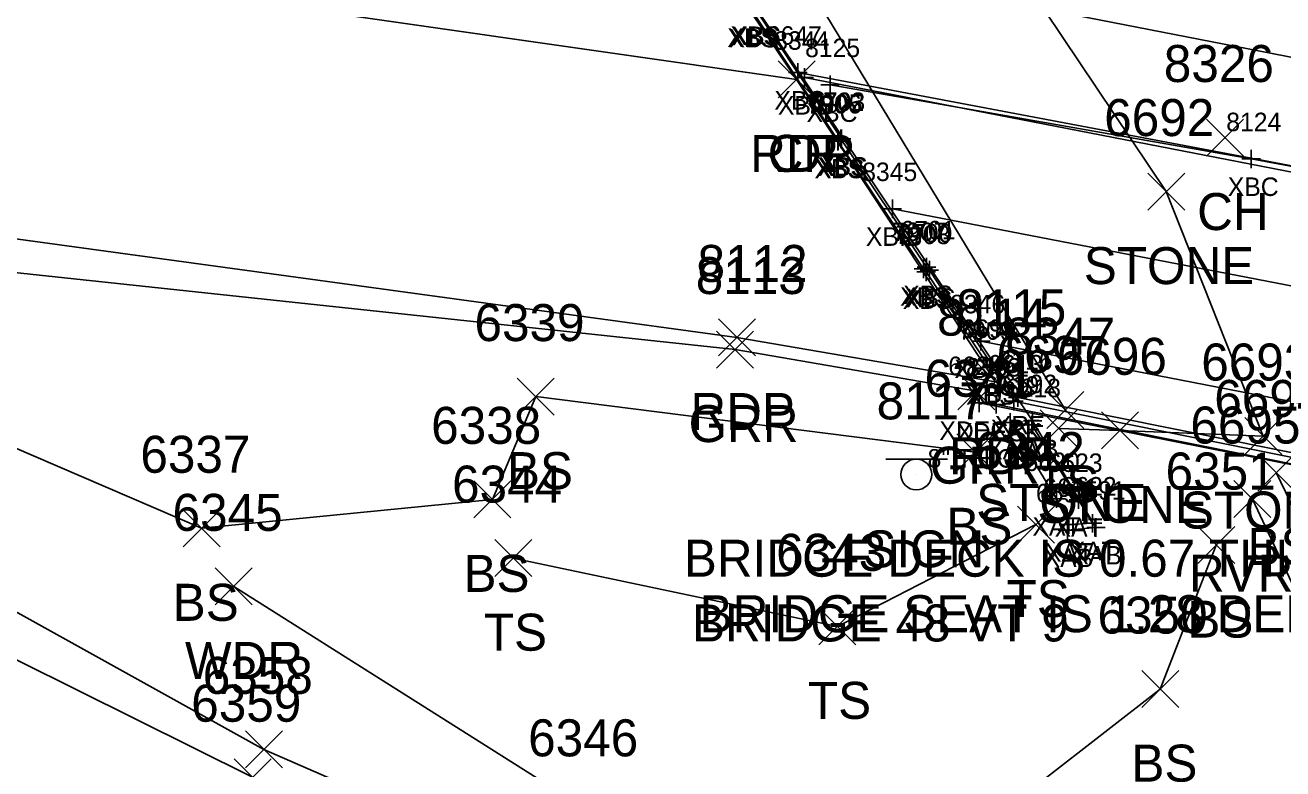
# Model space of a CAD drawing. Extents: x 1588028 to 1589597, y 137576 to 138176.
# Drawn here: x 1588875.5 to 1588943.5, y 137826.6 to 137866.8 of the extents above; entities that cross this region are included whole.
import ezdxf

# ---------------------------------------------------------------- set-up
doc = ezdxf.new("R2010")
doc.units = 0
for name, color, linetype in [('B_A', 7, 'Continuous'), ('B_C', 7, 'Continuous'), ('B_I', 7, 'Continuous'), ('B_TIC', 7, 'Continuous'), ('BB', 7, 'Continuous'), ('BELB', 7, 'Continuous'), ('BR', 7, 'Continuous'), ('BSE', 7, 'Continuous'), ('BSUBM', 7, 'Continuous'), ('L_A', 7, 'Continuous'), ('L_C', 7, 'Continuous'), ('L_I', 7, 'Continuous'), ('L_TIC', 7, 'Continuous'), ('LASF', 7, 'Continuous'), ('LAWA', 7, 'Continuous'), ('LAWE', 7, 'Continuous'), ('LELB', 7, 'Continuous'), ('P_A', 7, 'Continuous'), ('P_I', 7, 'Continuous'), ('P_TIC', 7, 'Continuous'), ('PET', 7, 'Continuous'), ('PRC', 7, 'Continuous'), ('R_A', 7, 'Continuous'), ('R_I', 7, 'Continuous'), ('R_TIC', 7, 'Continuous'), ('RGR', 7, 'Continuous'), ('S_A', 7, 'Continuous'), ('S_C', 7, 'Continuous'), ('S_I', 7, 'Continuous'), ('SSGN', 7, 'Continuous')]:
    doc.layers.add(name, color=color, linetype=linetype)

msp = doc.modelspace()

# ---------------------------------------------------------------- linework, layer by layer
at = {"layer": 'B_TIC'}
for p, q in [((1588917.306, 137864.223), (1588917.382, 137864.223)), ((1588917.661, 137863.951), (1588917.737, 137863.951)), ((1588919.047, 137863.553), (1588919.123, 137863.553)), ((1588919.475, 137860.508), (1588919.55, 137860.508)), ((1588919.492, 137860.544), (1588919.567, 137860.544)), ((1588919.625, 137860.635), (1588919.701, 137860.635)), ((1588919.666, 137860.644), (1588919.742, 137860.644)), ((1588941.815, 137859.552), (1588941.89, 137859.552)), ((1588922.419, 137856.857), (1588922.494, 137856.857)), ((1588924.267, 137853.707), (1588924.342, 137853.707)), ((1588924.095, 137853.616), (1588924.17, 137853.616)), ((1588924.244, 137853.45), (1588924.319, 137853.45)), ((1588924.42, 137853.54), (1588924.495, 137853.54)), ((1588927.2, 137849.709), (1588927.276, 137849.709)), ((1588927.664, 137848.28), (1588927.74, 137848.28)), ((1588927.829, 137848.377), (1588927.905, 137848.377)), ((1588927.118, 137846.372), (1588927.193, 137846.372)), ((1588928.033, 137846.292), (1588928.108, 137846.292)), ((1588928.98, 137846.459), (1588929.056, 137846.459)), ((1588929.195, 137846.665), (1588929.271, 137846.665)), ((1588928.786, 137845.314), (1588928.861, 137845.314)), ((1588929.949, 137845.177), (1588930.025, 137845.177)), ((1588930.001, 137845.393), (1588930.077, 137845.393)), ((1588931.286, 137841.191), (1588931.362, 137841.191)), ((1588932.485, 137841.138), (1588932.56, 137841.138)), ((1588931.878, 137839.494), (1588931.954, 137839.494)), ((1588931.963, 137839.791), (1588932.039, 137839.791)), ((1588933.239, 137839.863), (1588933.314, 137839.863)), ((1588933.427, 137839.638), (1588933.502, 137839.638))]:
    msp.add_line(p, q, dxfattribs=at)
for points in [[(1588917.303, 137863.723), (1588917.303, 137864.723)], [(1588916.803, 137864.223), (1588917.803, 137864.223)], [(1588917.158, 137863.951), (1588918.158, 137863.951)], [(1588917.658, 137863.451), (1588917.658, 137864.451)], [(1588919.044, 137863.053), (1588919.044, 137864.053)], [(1588918.544, 137863.553), (1588919.544, 137863.553)], [(1588918.971, 137860.508), (1588919.971, 137860.508)], [(1588918.988, 137860.544), (1588919.988, 137860.544)], [(1588919.122, 137860.635), (1588920.122, 137860.635)], [(1588919.163, 137860.644), (1588920.163, 137860.644)], [(1588919.471, 137860.008), (1588919.471, 137861.008)], [(1588919.488, 137860.044), (1588919.488, 137861.044)], [(1588919.622, 137860.135), (1588919.622, 137861.135)], [(1588919.663, 137860.144), (1588919.663, 137861.144)], [(1588941.811, 137859.052), (1588941.811, 137860.052)], [(1588941.311, 137859.552), (1588942.311, 137859.552)], [(1588922.415, 137856.357), (1588922.415, 137857.357)], [(1588921.915, 137856.857), (1588922.915, 137856.857)], [(1588923.763, 137853.707), (1588924.763, 137853.707)], [(1588924.091, 137853.116), (1588924.091, 137854.116)], [(1588924.24, 137852.95), (1588924.24, 137853.95)], [(1588924.263, 137853.207), (1588924.263, 137854.207)], [(1588924.416, 137853.04), (1588924.416, 137854.04)], [(1588923.591, 137853.616), (1588924.591, 137853.616)], [(1588923.74, 137853.45), (1588924.74, 137853.45)], [(1588923.916, 137853.54), (1588924.916, 137853.54)], [(1588926.697, 137849.709), (1588927.697, 137849.709)], [(1588927.197, 137849.209), (1588927.197, 137850.209)], [(1588927.161, 137848.28), (1588928.161, 137848.28)], [(1588927.326, 137848.377), (1588928.326, 137848.377)], [(1588927.661, 137847.78), (1588927.661, 137848.78)], [(1588927.826, 137847.877), (1588927.826, 137848.877)], [(1588928.977, 137845.959), (1588928.977, 137846.959)], [(1588929.192, 137846.165), (1588929.192, 137847.165)], [(1588926.614, 137846.372), (1588927.614, 137846.372)], [(1588927.114, 137845.872), (1588927.114, 137846.872)], [(1588927.529, 137846.292), (1588928.529, 137846.292)], [(1588928.029, 137845.792), (1588928.029, 137846.792)], [(1588928.477, 137846.459), (1588929.477, 137846.459)], [(1588928.692, 137846.665), (1588929.692, 137846.665)], [(1588928.782, 137844.814), (1588928.782, 137845.814)], [(1588929.946, 137844.677), (1588929.946, 137845.677)], [(1588929.998, 137844.893), (1588929.998, 137845.893)], [(1588928.282, 137845.314), (1588929.282, 137845.314)], [(1588929.446, 137845.177), (1588930.446, 137845.177)], [(1588929.498, 137845.393), (1588930.498, 137845.393)], [(1588931.283, 137840.691), (1588931.283, 137841.691)], [(1588932.481, 137840.638), (1588932.481, 137841.638)], [(1588930.783, 137841.191), (1588931.783, 137841.191)], [(1588931.981, 137841.138), (1588932.981, 137841.138)], [(1588931.96, 137839.291), (1588931.96, 137840.291)], [(1588933.235, 137839.363), (1588933.235, 137840.363)], [(1588933.423, 137839.138), (1588933.423, 137840.138)], [(1588931.375, 137839.494), (1588932.375, 137839.494)], [(1588931.46, 137839.791), (1588932.46, 137839.791)], [(1588931.875, 137838.994), (1588931.875, 137839.994)], [(1588932.735, 137839.863), (1588933.735, 137839.863)], [(1588932.923, 137839.638), (1588933.923, 137839.638)]]:
    msp.add_lwpolyline(points, dxfattribs=at)
at = {"layer": 'BB'}
for points in [[(1588959.799, 137861.973), (1588912.85, 137871.124)], [(1588964.615, 137854.84), (1588917.658, 137863.951)], [(1588969.321, 137847.789), (1588922.415, 137856.857)], [(1588973.921, 137840.635), (1588927.197, 137849.709)]]:
    msp.add_lwpolyline(points, dxfattribs=at)
at = {"layer": 'BELB'}
for points in [[(1588917.303, 137864.223), (1588964.402, 137855.327)], [(1588963.452, 137855.546), (1588941.811, 137859.552), (1588919.044, 137863.553)], [(1588927.114, 137846.372), (1588979.371, 137836.039)], [(1588928.029, 137846.292), (1588979.202, 137836)]]:
    msp.add_lwpolyline(points, dxfattribs=at)
at = {"layer": 'BR'}
for points in [[(1588977.852, 137836.609), (1588956.329, 137840.938), (1588928.977, 137846.459)], [(1588929.192, 137846.665), (1588951.225, 137842.233), (1588976.257, 137837.185)]]:
    msp.add_lwpolyline(points, dxfattribs=at)
at = {"layer": 'BSE'}
for points in [[(1588927.826, 137848.377), (1588924.416, 137853.54), (1588924.263, 137853.707), (1588919.622, 137860.635), (1588919.663, 137860.644), (1588914.984, 137867.694), (1588914.921, 137867.712), (1588910.295, 137874.708), (1588910.112, 137874.897), (1588907.238, 137879.288), (1588907.072, 137879.191), (1588909.942, 137874.794), (1588910.127, 137874.607), (1588914.754, 137867.602), (1588914.823, 137867.578), (1588919.488, 137860.544), (1588919.471, 137860.508), (1588924.091, 137853.616), (1588924.24, 137853.45), (1588927.661, 137848.28)], [(1588927.661, 137848.28), (1588927.826, 137848.377)]]:
    msp.add_lwpolyline(points, dxfattribs=at)
at = {"layer": 'BSUBM'}
for points in [[(1588931.875, 137839.494), (1588933.423, 137839.638), (1588929.998, 137845.393), (1588905.049, 137882.647), (1588900.791, 137888.794), (1588898.55, 137889.157)], [(1588929.946, 137845.177), (1588928.782, 137845.314), (1588931.283, 137841.191), (1588931.96, 137839.791), (1588933.235, 137839.863), (1588932.481, 137841.138)], [(1588932.481, 137841.138), (1588929.946, 137845.177)]]:
    msp.add_lwpolyline(points, dxfattribs=at)
at = {"layer": 'L_TIC'}
for points in [[(1588939.404, 137859.709), (1588941.404, 137861.709)], [(1588941.404, 137859.709), (1588939.404, 137861.709)], [(1588936.221, 137856.788), (1588938.221, 137858.788)], [(1588938.221, 137856.788), (1588936.221, 137858.788)], [(1588902.141, 137845.709), (1588904.141, 137847.709)], [(1588904.141, 137845.709), (1588902.141, 137847.709)], [(1588930.773, 137844.978), (1588932.773, 137846.978)], [(1588932.773, 137844.978), (1588930.773, 137846.978)], [(1588930.403, 137843.992), (1588932.403, 137845.992)], [(1588932.403, 137843.992), (1588930.403, 137845.992)], [(1588933.714, 137843.887), (1588935.714, 137845.887)], [(1588935.714, 137843.887), (1588933.714, 137845.887)], [(1588941.468, 137843.578), (1588943.468, 137845.578)], [(1588943.468, 137843.578), (1588941.468, 137845.578)], [(1588925.895, 137842.703), (1588927.895, 137844.703)], [(1588927.895, 137842.703), (1588925.895, 137844.703)], [(1588942.171, 137841.608), (1588944.171, 137843.608)], [(1588944.171, 137841.608), (1588942.171, 137843.608)], [(1588899.791, 137840.156), (1588901.791, 137842.156)], [(1588901.791, 137840.156), (1588899.791, 137842.156)], [(1588940.88, 137840.174), (1588942.88, 137842.174)], [(1588942.88, 137840.174), (1588940.88, 137842.174)], [(1588929.178, 137838.795), (1588931.178, 137840.795)], [(1588931.178, 137838.795), (1588929.178, 137840.795)], [(1588884.071, 137838.593), (1588886.071, 137840.593)], [(1588886.071, 137838.593), (1588884.071, 137840.593)], [(1588938.924, 137837.687), (1588940.924, 137839.687)], [(1588940.924, 137837.687), (1588938.924, 137839.687)], [(1588900.92, 137836.98), (1588902.92, 137838.98)], [(1588902.92, 137836.98), (1588900.92, 137838.98)], [(1588885.811, 137835.455), (1588887.811, 137837.455)], [(1588887.811, 137835.455), (1588885.811, 137837.455)], [(1588918.441, 137833.296), (1588920.441, 137835.296)], [(1588920.441, 137833.296), (1588918.441, 137835.296)], [(1588935.899, 137829.904), (1588937.899, 137831.904)], [(1588937.899, 137829.904), (1588935.899, 137831.904)], [(1588887.445, 137826.646), (1588889.445, 137828.646)], [(1588889.445, 137826.646), (1588887.445, 137828.646)], [(1588886.83, 137825.142), (1588888.83, 137827.142)], [(1588888.83, 137825.142), (1588886.83, 137827.142)]]:
    msp.add_lwpolyline(points, dxfattribs=at)
at = {"layer": 'LASF'}
msp.add_lwpolyline([(1588911.174, 137880.705), (1588913.559, 137879.473), (1588925.059, 137875.931), (1588937.221, 137857.788), (1588942.468, 137844.578), (1588934.714, 137844.887), (1588931.403, 137844.992)], dxfattribs=at)
at = {"layer": 'LAWA'}
msp.add_lwpolyline([(1588886.811, 137836.455), (1588906.089, 137824.27), (1588922.461, 137819.292), (1588938.14, 137818.463)], dxfattribs=at)
at = {"layer": 'LAWE'}
for points in [[(1588977.094, 137801.88), (1588949.989, 137800.551), (1588913.527, 137816.705), (1588888.445, 137827.646), (1588864.1, 137841.148), (1588838.93, 137847.705), (1588814.529, 137847.159), (1588788.404, 137846.571), (1588760.058, 137845.853), (1588744.309, 137852.311), (1588711.694, 137843.681)], [(1588941.88, 137841.174), (1588949.924, 137824.068), (1588963.725, 137811.706), (1588978.436, 137804.59)]]:
    msp.add_lwpolyline(points, dxfattribs=at)
at = {"layer": 'LELB'}
for points in [[(1588911.531, 137879.394), (1588931.773, 137845.978)], [(1588833.83, 137853.278), (1588867.011, 137847.363), (1588885.071, 137839.593), (1588900.791, 137841.156), (1588903.141, 137846.709), (1588926.895, 137843.703)], [(1588976.952, 137800.762), (1588950.622, 137796.897), (1588914.436, 137812.099), (1588887.83, 137826.142), (1588862.587, 137838.676), (1588839.41, 137844.479), (1588814.279, 137844.579), (1588790.418, 137844.541), (1588761.499, 137843.618), (1588744.062, 137845.907), (1588711.096, 137839.153), (1588710.72, 137829.123), (1588738.022, 137826.67), (1588767.074, 137829.2), (1588800.854, 137829.837), (1588826.76, 137827.942), (1588856.442, 137818.616), (1588893.47, 137804.611), (1588923.152, 137792.66), (1588953.978, 137786.083), (1588988.158, 137786.332)], [(1588943.171, 137842.608), (1588952.372, 137823.531), (1588964.918, 137812.896), (1588979.766, 137805.361)], [(1588930.178, 137839.795), (1588919.441, 137834.296), (1588901.92, 137837.98)], [(1588924.282, 137821.11), (1588936.899, 137830.904), (1588939.924, 137838.687)]]:
    msp.add_lwpolyline(points, dxfattribs=at)
at = {"layer": 'P_TIC'}
for points in [[(1588916.24, 137862.853), (1588918.24, 137864.853)], [(1588918.24, 137862.853), (1588916.24, 137864.853)], [(1588916.24, 137862.853), (1588918.24, 137864.853)], [(1588918.24, 137862.853), (1588916.24, 137864.853)], [(1588913.011, 137848.905), (1588915.011, 137850.905)], [(1588915.011, 137848.905), (1588913.011, 137850.905)], [(1588926.992, 137846.51), (1588928.992, 137848.51)], [(1588928.992, 137846.51), (1588926.992, 137848.51)], [(1588926.992, 137846.51), (1588928.992, 137848.51)], [(1588928.992, 137846.51), (1588926.992, 137848.51)]]:
    msp.add_lwpolyline(points, dxfattribs=at)
at = {"layer": 'PET'}
for points in [[(1588422.162, 137923.17), (1588469.198, 137920.726), (1588503.282, 137919.24), (1588517.546, 137918.562), (1588549.936, 137917.247), (1588592.353, 137915.11), (1588643.263, 137911.753), (1588663.499, 137910.854), (1588704.319, 137908.351), (1588747.195, 137904.384), (1588787.693, 137899.079), (1588825.325, 137893.626), (1588865.15, 137887.82), (1588905.816, 137880.769), (1588917.24, 137863.853), (1588927.992, 137847.51)], [(1588419.971, 137892.513), (1588466.094, 137889.908), (1588506.756, 137888.014), (1588547.996, 137885.778), (1588590.45, 137883.611), (1588638.454, 137880.687), (1588661.688, 137879.382), (1588677.514, 137878.09), (1588721.126, 137874.784), (1588740.191, 137872.991), (1588782.635, 137867.931), (1588820.212, 137862.867), (1588860.264, 137857.259), (1588914.011, 137849.905), (1588927.992, 137847.51)]]:
    msp.add_lwpolyline(points, dxfattribs=at)
at = {"layer": 'PRC'}
msp.add_lwpolyline([(1588420.991, 137907.197), (1588467.18, 137904.915), (1588507.288, 137903.206), (1588549.369, 137901.189), (1588590.546, 137899.296), (1588641.569, 137896.105), (1588661.527, 137894.877), (1588702.386, 137891.263), (1588744.444, 137887.15), (1588784.396, 137882.299), (1588823.706, 137877.304), (1588862.063, 137871.744), (1588917.24, 137863.853)], dxfattribs=at)
at = {"layer": 'R_TIC'}
for points in [[(1588912.913, 137848.252), (1588914.913, 137850.252)], [(1588914.913, 137848.252), (1588912.913, 137850.252)], [(1588925.956, 137846.004), (1588927.956, 137848.004)], [(1588927.956, 137846.004), (1588925.956, 137848.004)]]:
    msp.add_lwpolyline(points, dxfattribs=at)
at = {"layer": 'RGR'}
msp.add_lwpolyline([(1588840.122, 137856.162), (1588859.772, 137855.037), (1588913.913, 137849.252), (1588926.956, 137847.004)], dxfattribs=at)
at = {"layer": 'SSGN'}
for p, q in [((1588922.062, 137843.332), (1588925.396, 137843.332)), ((1588923.709, 137842.499), (1588923.709, 137842.499))]:
    msp.add_line(p, q, dxfattribs=at)
msp.add_circle((1588923.709, 137842.499), 0.833, dxfattribs=at)

# ---------------------------------------------------------------- texts
at = {"layer": 'B_A'}
for s, p in [('XBS', (1588913.494, 137865.602)), ('XBS', (1588913.661, 137865.712)), ('XBS', (1588913.724, 137865.694)), ('XBS', (1588913.563, 137865.578)), ('XBC', (1588916.039, 137862.223)), ('XBIB', (1588916.228, 137861.951)), ('XBC', (1588917.78, 137861.553)), ('XBS', (1588918.212, 137858.508)), ('XBS', (1588918.228, 137858.544)), ('XBS', (1588918.362, 137858.635)), ('XBS', (1588918.403, 137858.644)), ('XBC', (1588940.548, 137857.552)), ('XBIB', (1588920.986, 137854.857)), ('XBS', (1588922.831, 137851.616)), ('XBS', (1588922.98, 137851.45)), ('XBS', (1588923.003, 137851.707)), ('XBS', (1588923.156, 137851.54)), ('XBIB', (1588925.768, 137847.709)), ('XBS', (1588926.401, 137846.28)), ('XBS', (1588926.566, 137846.377)), ('XRF', (1588927.951, 137844.665)), ('XDECK', (1588924.957, 137844.372)), ('XDECK', (1588925.872, 137844.292)), ('XRF', (1588927.737, 137844.459)), ('XAT', (1588927.487, 137843.314)), ('XAT', (1588928.65, 137843.177)), ('XAB', (1588928.718, 137843.393)), ('XAT', (1588929.987, 137839.191)), ('XAT', (1588931.186, 137839.138)), ('XAT', (1588930.665, 137837.791)), ('XAT', (1588931.94, 137837.863)), ('XAB', (1588930.595, 137837.494)), ('XAB', (1588932.144, 137837.638))]:
    msp.add_text(s, height=1, dxfattribs=at).set_placement(p)
at = {"layer": 'B_C'}
msp.add_text('8" THICK', height=1, dxfattribs=at).set_placement((1588924.319, 137842.872))
at = {"layer": 'B_I'}
for s, p in [('6647', (1588915.625, 137865.723)), ('8344', (1588916.028, 137865.451)), ('8125', (1588917.697, 137865.053)), ('7906', (1588917.775, 137862.008)), ('7905', (1588917.819, 137862.044)), ('6702', (1588917.929, 137862.135)), ('6703', (1588917.97, 137862.144)), ('8124', (1588940.465, 137861.052)), ('8345', (1588920.785, 137858.357)), ('7907', (1588922.422, 137855.116)), ('7908', (1588922.571, 137854.95)), ('6700', (1588922.68, 137855.04)), ('6701', (1588922.854, 137855.207)), ('8346', (1588925.539, 137851.209)), ('7909', (1588925.988, 137849.78)), ('6699', (1588926.145, 137849.877)), ('6613', (1588927.583, 137847.959)), ('8116', (1588928.101, 137848.165)), ('6624', (1588925.437, 137847.872)), ('8383', (1588926.399, 137847.792)), ('6619', (1588927.385, 137846.814)), ('6592', (1588928.344, 137846.893)), ('6618', (1588928.552, 137846.677)), ('6620', (1588929.562, 137842.691)), ('6623', (1588930.804, 137842.638)), ('6621', (1588930.566, 137841.291)), ('6622', (1588931.558, 137841.363)), ('6591', (1588932.053, 137841.138)), ('6590', (1588930.178, 137840.994))]:
    msp.add_text(s, height=1, dxfattribs=at).set_placement(p)
at = {"layer": 'L_A'}
for s, p in [('CH', (1588938.892, 137855.709)), ('STONE', (1588932.765, 137852.788)), ('BS', (1588901.582, 137841.709)), ('TS', (1588930.183, 137840.978)), ('STONE', (1588926.946, 137839.992)), ('STONE', (1588930.257, 137839.887)), ('STONE', (1588938.012, 137839.578)), ('BS', (1588925.336, 137838.703)), ('BS', (1588941.612, 137837.608)), ('BS', (1588899.232, 137836.156)), ('RVRL', (1588938.447, 137836.174)), ('TS', (1588928.588, 137834.795)), ('BS', (1588883.512, 137834.593)), ('BS', (1588938.365, 137833.687)), ('TS', (1588900.33, 137832.98)), ('WDR', (1588884.174, 137831.455)), ('TS', (1588917.851, 137829.296)), ('BS', (1588935.339, 137825.904))]:
    msp.add_text(s, height=2, dxfattribs=at).set_placement(p)
at = {"layer": 'L_C'}
for s, p in [('BRIDGE DECK IS 0.67 THICK', (1588911.143, 137836.978)), ('BRIDGE SEAT IS 1.28 DEEP', (1588912.001, 137833.978))]:
    msp.add_text(s, height=2, dxfattribs=at).set_placement(p)
at = {"layer": 'L_I'}
for s, p in [('8326', (1588937.089, 137863.709)), ('6692', (1588933.867, 137860.788)), ('6339', (1588899.826, 137849.709)), ('8347', (1588928.513, 137848.978)), ('6697', (1588928.049, 137847.992)), ('6696', (1588931.304, 137847.887)), ('6693', (1588939.114, 137847.578)), ('6341', (1588924.155, 137846.703)), ('6694', (1588939.817, 137845.608)), ('6338', (1588897.484, 137844.156)), ('6695', (1588938.526, 137844.174)), ('6337', (1588881.764, 137842.593)), ('6342', (1588926.871, 137842.795)), ('6351', (1588937.184, 137841.687)), ('6344', (1588898.613, 137840.98)), ('6345', (1588883.504, 137839.455)), ('6343', (1588916.134, 137837.296)), ('6350', (1588933.505, 137833.904)), ('6358', (1588885.137, 137830.646)), ('6359', (1588884.515, 137829.142)), ('6346', (1588902.727, 137827.27))]:
    msp.add_text(s, height=2, dxfattribs=at).set_placement(p)
at = {"layer": 'P_A'}
for s, p in [('RDP', (1588914.728, 137858.853)), ('CR', (1588915.673, 137858.853)), ('RDP', (1588911.5, 137844.905)), ('RDP', (1588925.481, 137842.51)), ('RDP', (1588925.481, 137842.51))]:
    msp.add_text(s, height=2, dxfattribs=at).set_placement(p)
at = {"layer": 'P_I'}
for s, p in [('8112', (1588911.885, 137852.905)), ('8115', (1588925.866, 137850.51)), ('8115', (1588925.866, 137850.51))]:
    msp.add_text(s, height=2, dxfattribs=at).set_placement(p)
at = {"layer": 'R_A'}
for p in [(1588911.401, 137844.252), (1588924.444, 137842.004)]:
    msp.add_text('GRR', height=2, dxfattribs=at).set_placement(p)
at = {"layer": 'R_I'}
for s, p in [('8113', (1588911.787, 137852.252)), ('8114', (1588924.83, 137850.004))]:
    msp.add_text(s, height=2, dxfattribs=at).set_placement(p)
at = {"layer": 'S_A'}
msp.add_text('SIGN', height=2, dxfattribs=at).set_placement((1588920.847, 137837.479))
at = {"layer": 'S_C'}
msp.add_text('BRIDGE 48 VT 9', height=2, dxfattribs=at).set_placement((1588911.587, 137833.479))
at = {"layer": 'S_I'}
msp.add_text('8117', height=2, dxfattribs=at).set_placement((1588921.564, 137845.479))

doc.saveas('drawing.dxf')
